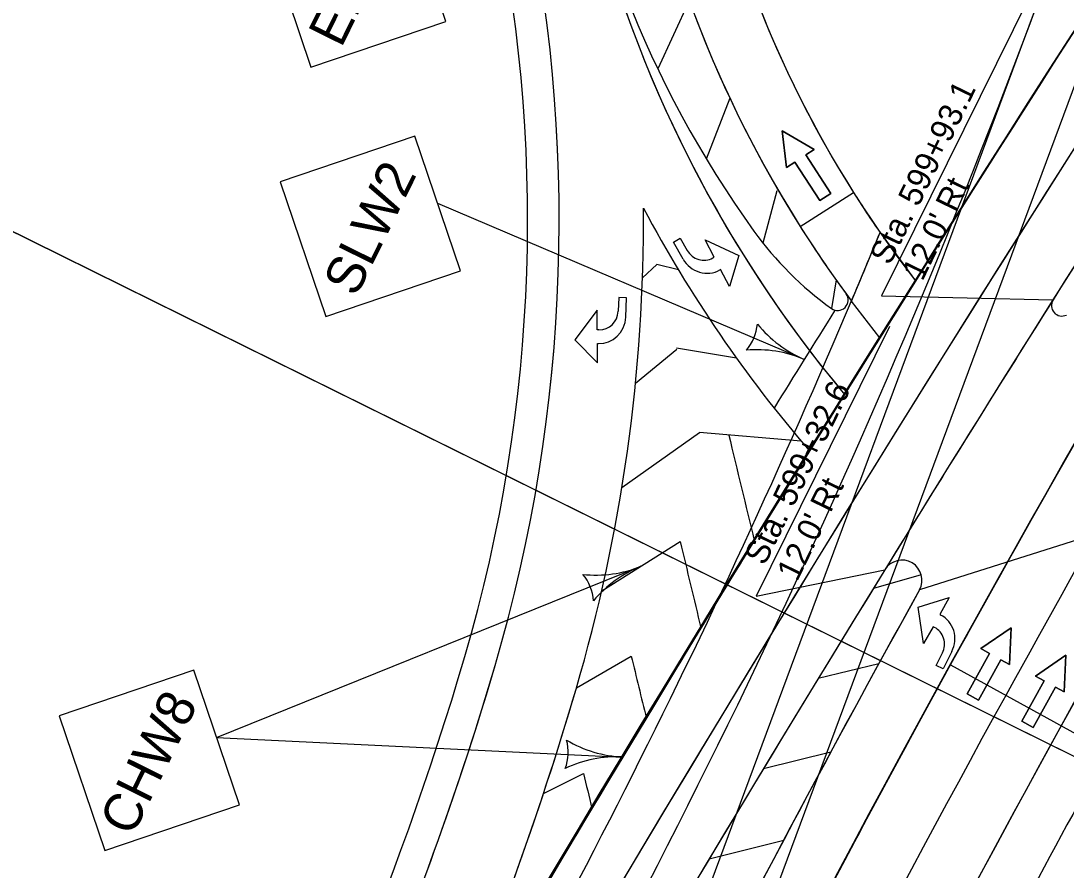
# Model space of a CAD drawing. Extents: x 14097936 to 14128734, y 8632000 to 8683104.
# Drawn here: x 14118895.5 to 14119093.8, y 8668694.3 to 8668855.4 of the extents above; entities that cross this region are included whole.
import ezdxf

# ---------------------------------------------------------------- set-up
doc = ezdxf.new("R2010")
doc.units = 0
for name, color, linetype in [('Cell', 7, 'Continuous'), ('dsn_stg_shd_prev', 7, 'Continuous'), ('dsnNonPlotable', 7, 'Continuous'), ('dsnPaintExistingChannelizingLaneWhite', 7, 'Continuous'), ('dsnPaintExistingChannelizingLaneYellow', 7, 'Continuous'), ('dsnPaintExistingEdgeLineRightWhite', 7, 'Continuous'), ('dsnPaintPlaceBrokenLaneWhite', 7, 'Continuous'), ('dsnPaintPlaceChannelizingLaneWhite', 7, 'Continuous'), ('dsnPaintPlaceChannelizingLaneYellow', 7, 'Continuous'), ('dsnPaintPlaceEdgeLineRightWhite', 7, 'Continuous'), ('dsnPaintPlaceLaneLineWhite', 7, 'Continuous'), ('dsnPaintPlaceStopLineWhite', 7, 'Continuous'), ('dsnShadingPaved', 7, 'Continuous'), ('dsnStdLabel', 7, 'Continuous'), ('dsnStgShadingPrevPav', 7, 'Continuous'), ('dsnStgShadingPropPav', 7, 'Continuous'), ('dsnTapeRemoveChannelizingLaneWhite', 7, 'Continuous'), ('dsnTapeRemoveChannelizingLaneYellow', 7, 'Continuous'), ('Level 2', 7, 'Continuous'), ('Level 5', 7, 'Continuous'), ('Text', 7, 'Continuous')]:
    doc.layers.add(name, color=color, linetype=linetype)

msp = doc.modelspace()

# ---------------------------------------------------------------- linework, layer by layer
at = {"layer": 'Cell'}
for p, q in [((14119026.79, 8668810.43), (14119027.06, 8668810.59)), ((14119028.26, 8668808.25), (14119028.11, 8668808.16)), ((14119005.19, 8668796.79), (14119004.88, 8668796.8)), ((14119004.89, 8668794.17), (14119005.08, 8668794.16)), ((14119069.86, 8668742.74), (14119070.03, 8668742.66)), ((14119068.86, 8668740.3), (14119068.58, 8668740.44))]:
    msp.add_line(p, q, dxfattribs=at)
for points in [[(14119021.16, 8668810.2), (14119019.31, 8668813.39), (14119020.61, 8668814.14), (14119021.92, 8668811.86)], [(14119021.16, 8668810.2), (14119019.31, 8668813.39), (14119020.61, 8668814.14), (14119021.92, 8668811.86)], [(14119027.06, 8668810.59), (14119025.37, 8668813.86), (14119031.72, 8668810.86)], [(14119027.06, 8668810.59), (14119025.37, 8668813.86), (14119031.72, 8668810.86)], [(14119026.79, 8668810.43), (14119027.06, 8668810.59)], [(14119031.72, 8668810.86), (14119029.95, 8668804.97), (14119028.26, 8668808.25)], [(14119031.72, 8668810.86), (14119029.95, 8668804.97), (14119028.26, 8668808.25)], [(14119028.26, 8668808.25), (14119028.11, 8668808.16)], [(14119010.28, 8668799.19), (14119010.45, 8668802.87), (14119008.96, 8668802.93), (14119008.84, 8668800.31)], [(14119010.28, 8668799.19), (14119010.45, 8668802.87), (14119008.96, 8668802.93), (14119008.84, 8668800.31)], [(14119004.88, 8668796.8), (14119004.86, 8668800.48), (14119000.62, 8668794.88)], [(14119004.88, 8668796.8), (14119004.86, 8668800.48), (14119000.62, 8668794.88)], [(14119005.19, 8668796.79), (14119004.88, 8668796.8)], [(14119000.62, 8668794.88), (14119004.91, 8668790.48), (14119004.89, 8668794.17)], [(14119000.62, 8668794.88), (14119004.91, 8668790.48), (14119004.89, 8668794.17)], [(14119004.89, 8668794.17), (14119005.08, 8668794.16)], [(14119065.78, 8668744.17), (14119071.66, 8668745.95), (14119069.86, 8668742.74)], [(14119065.78, 8668744.17), (14119071.66, 8668745.95), (14119069.86, 8668742.74)], [(14119068.58, 8668740.44), (14119066.78, 8668737.22), (14119065.78, 8668744.17)], [(14119068.58, 8668740.44), (14119066.78, 8668737.22), (14119065.78, 8668744.17)], [(14119069.86, 8668742.74), (14119070.03, 8668742.66)], [(14119068.86, 8668740.3), (14119068.58, 8668740.44)], [(14119072.16, 8668735.74), (14119070.53, 8668732.44), (14119069.19, 8668733.1), (14119070.36, 8668735.46)], [(14119072.16, 8668735.74), (14119070.53, 8668732.44), (14119069.19, 8668733.1), (14119070.36, 8668735.46)]]:
    msp.add_lwpolyline(points, dxfattribs=at)
for centre, major_axis, start_param, end_param in [((14119024.94, 8668813.61), (-1.85, 3.18), 1.570796, 3.141593), ((14119024.94, 8668813.61), (-1.85, 3.18), 1.570796, 3.141593), ((14119025.47, 8668812.7), (-2.64, 4.55), 1.570796, 3.141593), ((14119025.47, 8668812.7), (-2.64, 4.55), 1.570796, 3.141593), ((14119005.36, 8668800.46), (0.16, 3.68), 3.141593, 4.712389), ((14119005.36, 8668800.46), (0.16, 3.68), 3.141593, 4.712389), ((14119005.31, 8668799.41), (0.23, 5.25), 3.141593, 4.712389), ((14119005.31, 8668799.41), (0.23, 5.25), 3.141593, 4.712389), ((14119067.7, 8668737.94), (-2.33, -4.71), 1.570796, 3.141593), ((14119067.7, 8668737.94), (-2.33, -4.71), 1.570796, 3.141593), ((14119067.23, 8668737), (-1.63, -3.3), 1.570796, 3.141593), ((14119067.23, 8668737), (-1.63, -3.3), 1.570796, 3.141593)]:
    msp.add_ellipse(centre, major_axis=major_axis, ratio=0.9474, start_param=start_param, end_param=end_param, dxfattribs=at)
at = {"layer": 'dsn_stg_shd_prev'}
msp.add_line((14119071.87, 8668733.2), (14119101.66, 8668716.8), dxfattribs=at)
for centre, radius, start, end in [((14123732.59, 8665873.82), 5512, 146.41866, 157.1633), ((14123732.59, 8665873.82), 5512, 146.50213, 150.36196), ((14121592.11, 8667345.68), 2876.95, 147.23628, 151.16499), ((14121591.75, 8667345.11), 2876.96, 147.23629, 155.33788), ((14118697.65, 8668817.62), 294, 343.6304, 12.5104), ((14118409.81, 8668902.17), 594, 330.3689, 343.63038)]:
    msp.add_arc(centre, radius, start, end, dxfattribs=at)
at = {"layer": 'dsnNonPlotable'}
for points in [[(14118631.64, 8668945.1), (14119326.37, 8670350.23), (14120231.75, 8669902.59), (14119537.02, 8668497.46)], [(14119315.27, 8668607.09), (14120010, 8670012.23), (14119557.31, 8670236.05), (14118862.58, 8668830.91)]]:
    msp.add_lwpolyline(points, close=True, dxfattribs=at)
at = {"layer": 'dsnPaintExistingChannelizingLaneWhite'}
for centre, radius, start, end in [((14118697.65, 8668817.62), 316, 343.6304, 0.4076), ((14118409.81, 8668902.17), 616, 336.56541, 343.63038)]:
    msp.add_arc(centre, radius, start, end, dxfattribs=at)
at = {"layer": 'dsnPaintExistingChannelizingLaneYellow'}
for p, q in [((14119022.33, 8668859.19), (14119016.34, 8668846.32)), ((14119030.03, 8668840.74), (14119025.56, 8668829.19)), ((14119038.93, 8668823.15), (14119036.32, 8668813.23)), ((14119050.18, 8668806.25), (14119049.3, 8668800.81))]:
    msp.add_line(p, q, dxfattribs=at)
for centre, radius, start, end in [((14119196.84, 8668932.46), 200, 186.3366, 215.7802), ((14119233.62, 8668936.54), 225, 186.3042, 216.2139), ((14119087.32, 8668853.53), 65, 215.7802, 234.1997), ((14119050.47, 8668802.43), 2, 234.1997, 36.2139)]:
    msp.add_arc(centre, radius, start, end, dxfattribs=at)
at = {"layer": 'dsnPaintExistingEdgeLineRightWhite'}
for centre, radius, start, end in [((14118697.65, 8668817.62), 300, 343.6304, 12.5104), ((14118409.81, 8668902.17), 600, 334.79009, 343.63038)]:
    msp.add_arc(centre, radius, start, end, dxfattribs=at)
at = {"layer": 'dsnPaintPlaceBrokenLaneWhite'}
for centre, radius, start, end in [((14121592.11, 8667345.68), 2864.95, 147.15737, 151.16499), ((14123732.96, 8665874.38), 5500, 147.11705, 157.1633), ((14121592.11, 8667345.68), 2864.95, 151.16499, 157.1633)]:
    msp.add_arc(centre, radius, start, end, dxfattribs=at)
at = {"layer": 'dsnPaintPlaceChannelizingLaneWhite'}
for p, q in [((14119013.46, 8668806.63), (14119016.17, 8668809.17)), ((14119020.27, 8668808.15), (14119016.17, 8668809.17)), ((14119012.13, 8668786.68), (14119019.96, 8668793.09)), ((14119031.3, 8668791.39), (14119019.92, 8668793.27)), ((14119009.55, 8668766.85), (14119024.28, 8668777.3)), ((14119043.59, 8668775.63), (14119024.28, 8668777.3)), ((14119005.71, 8668747.22), (14119020.62, 8668756.58)), ((14119000.92, 8668728.83), (14119011.33, 8668734.86)), ((14118994.67, 8668708.79), (14119002.26, 8668712.6))]:
    msp.add_line(p, q, dxfattribs=at)
for centre, radius, start, end in [((14119233.62, 8668936.54), 249, 207.9416, 220.8109), ((14124361.64, 8670051.25), 5482, 193.44292, 193.6584), ((14123732.96, 8665874.38), 5512, 148.26304, 149.67774), ((14124353.66, 8670025.82), 5482, 193.38707, 193.56306), ((14124341.15, 8670017.58), 5482, 193.53196, 193.6584), ((14124330.84, 8670000.44), 5482, 193.58699, 193.6584)]:
    msp.add_arc(centre, radius, start, end, dxfattribs=at)
at = {"layer": 'dsnPaintPlaceChannelizingLaneYellow'}
for p, q in [((14119066.36, 8668750.3), (14119057.26, 8668747.71)), ((14119046.82, 8668730.65), (14119058.31, 8668733.44)), ((14119036.44, 8668713.55), (14119049.22, 8668716.7)), ((14119026.13, 8668696.42), (14119040.26, 8668699.96))]:
    msp.add_line(p, q, dxfattribs=at)
for centre, radius, start, end in [((14123732.96, 8665874.38), 5488, 146.41498, 147.75486), ((14119093.05, 8668801.39), 2, 147.7549, 295.2058), ((14119062.69, 8668749.26), 3.81, 330.9739, 148.3847), ((14123748.96, 8665864.73), 5506.68, 148.38653, 150.66501), ((14121592.11, 8667345.68), 2888.95, 150.97391, 155.3184)]:
    msp.add_arc(centre, radius, start, end, dxfattribs=at)
at = {"layer": 'dsnPaintPlaceEdgeLineRightWhite'}
for start, end in [(147.15737, 151.16499), (151.16499, 157.1633)]:
    msp.add_arc((14121592.11, 8667345.68), 2852.95, start, end, dxfattribs=at)
at = {"layer": 'dsnPaintPlaceLaneLineWhite'}
msp.add_arc((14121592.11, 8667345.68), 2876.95, 150.94619, 156.23387, dxfattribs=at)
at = {"layer": 'dsnPaintPlaceStopLineWhite'}
msp.add_arc((14123732.96, 8665874.38), 5522, 148.00263, 148.22799, dxfattribs=at)
at = {"layer": 'dsnShadingPaved'}
for p, q in [((14119043.37, 8668816.41), (14119053.52, 8668822.82)), ((14119043.37, 8668816.41), (14119053.52, 8668822.82)), ((14119058.5, 8668795.27), (14119053.1, 8668802.23)), ((14119051.8, 8668784.52), (14119058.5, 8668795.27)), ((14119045.16, 8668773.8), (14119051.8, 8668784.52))]:
    msp.add_line(p, q, dxfattribs=at)
msp.add_lwpolyline([(14119058.5, 8668795.27), (14119053.1, 8668802.23), (14119058.53, 8668815.24), (14119065.26, 8668806.06)], close=True, dxfattribs=at)
for centre, radius, start, end in [((14123732.96, 8665874.38), 5500, 145.2497, 157.1633), ((14123732.96, 8665874.38), 5488, 145.2497, 157.1633), ((14119233.62, 8668936.54), 237, 167.9329, 219.9002), ((14119233.62, 8668936.54), 225, 167.9329, 212.2703), ((14119233.62, 8668936.54), 225, 167.9329, 212.2703), ((14119233.62, 8668936.54), 213, 167.9329, 212.2703), ((14119233.62, 8668936.54), 213, 167.9329, 217.7768), ((14123732.96, 8665874.38), 5500, 146.42378, 157.1633), ((14121592.11, 8667345.68), 2876.95, 147.15737, 157.1633), ((14121592.11, 8667345.68), 2852.95, 147.15737, 157.1633), ((14123655.03, 8665915.77), 5424.12, 146.80648, 157.24675), ((14119233.62, 8668936.54), 237, 192.5105, 219.9002), ((14123056.19, 8666307.54), 4708.51, 146.80648, 147.95139), ((14118697.65, 8668817.62), 300, 343.6304, 12.5123), ((14119233.62, 8668936.54), 213, 212.2703, 214.7131), ((14121592.11, 8667345.68), 2876.95, 149.16283, 157.1633), ((14118697.65, 8668817.62), 316, 343.6304, 0.4076), ((14119233.62, 8668936.54), 249, 207.9416, 220.8109), ((14119233.62, 8668936.54), 225, 212.2703, 216.6514), ((14119233.62, 8668936.54), 225, 212.2703, 216.6514), ((14117682.33, 8669381.12), 1488, 337.10525, 337.64823), ((14123732.96, 8665874.38), 5488, 147.75486, 148.38471), ((14119093.05, 8668801.39), 2, 147.7549, 295.2058), ((14119062.69, 8668749.26), 3.81, 330.9739, 148.3847), ((14121592.11, 8667345.68), 2888.95, 150.97391, 156.23389), ((14118409.81, 8668902.17), 600, 330.3689, 343.63038), ((14118409.81, 8668902.17), 616, 336.78135, 343.63038)]:
    msp.add_arc(centre, radius, start, end, dxfattribs=at)
at = {"layer": 'dsnStdLabel'}
for p, q in [((14119044.16, 8668791.16), (14118974.6, 8668820.75)), ((14118932.65, 8668719.4), (14119013.16, 8668751.9)), ((14118932.65, 8668719.4), (14119009.72, 8668715.71))]:
    msp.add_line(p, q, dxfattribs=at)
for points in [[(14118950.54, 8668846.65), (14118976.12, 8668855.3), (14118967.47, 8668880.88), (14118941.89, 8668872.22)], [(14118953.35, 8668799.31), (14118978.92, 8668807.96), (14118970.27, 8668833.53), (14118944.7, 8668824.88)], [(14118911.4, 8668697.96), (14118936.97, 8668706.61), (14118928.32, 8668732.19), (14118902.74, 8668723.54)]]:
    msp.add_lwpolyline(points, close=True, dxfattribs=at)
for centre, radius, start, end in [((14119026.45, 8668798.69), 8.86, 319.2251, 354.6935), ((14119053.14, 8668812.28), 22.95, 218.8881, 246.9594), ((14119035.17, 8668770.04), 22.95, 66.9593, 95.0305), ((14119004.57, 8668773.18), 22.95, 263.909, 291.9803), ((14119021.75, 8668730.62), 22.95, 111.9801, 140.0514), ((14118995.32, 8668744.7), 8.86, 4.246, 39.7144), ((14118990.5, 8668716.63), 8.86, 339.5229, 14.9914), ((14119010.82, 8668738.63), 22.95, 239.1859, 267.2572), ((14119008.62, 8668692.79), 22.95, 87.2571, 115.3284)]:
    msp.add_arc(centre, radius, start, end, dxfattribs=at)
at = {"layer": 'dsnStgShadingPrevPav'}
for centre, radius, start, end in [((14123732.96, 8665874.38), 5512, 146.41866, 157.1633), ((14121592.12, 8667345.67), 2876.96, 147.23629, 155.33788)]:
    msp.add_arc(centre, radius, start, end, dxfattribs=at)
at = {"layer": 'dsnStgShadingPropPav'}
msp.add_line((14119071.87, 8668733.2), (14119101.66, 8668716.8), dxfattribs=at)
msp.add_line((14119071.87, 8668733.2), (14119101.66, 8668716.8), dxfattribs=at)
for centre, radius, start, end in [((14123732.59, 8665873.82), 5512, 146.50213, 150.36196), ((14121592.11, 8667345.68), 2876.95, 147.23628, 151.16499), ((14118697.65, 8668817.62), 294, 343.6304, 12.5104), ((14118409.81, 8668902.17), 594, 330.3689, 343.63038), ((14121592.11, 8667345.68), 2876.95, 151.16499, 152.63404), ((14121592.11, 8667345.68), 2842.95, 151.16499, 152.63404)]:
    msp.add_arc(centre, radius, start, end, dxfattribs=at)
at = {"layer": 'dsnTapeRemoveChannelizingLaneWhite'}
msp.add_line((14118983.04, 8668540.5), (14119108.11, 8668877.26), dxfattribs=at)
msp.add_arc((14117682.33, 8669381.12), 1488, 329.20119, 337.13903, dxfattribs=at)
at = {"layer": 'dsnTapeRemoveChannelizingLaneYellow'}
msp.add_line((14118971.78, 8668544.68), (14119088.49, 8668858.92), dxfattribs=at)
msp.add_arc((14117682.32, 8669381.12), 1500, 329.20119, 339.62671, dxfattribs=at)
at = {"layer": 'Level 2'}
for points in [[(14119047.11, 8668821.29), (14119049.21, 8668822.65), (14119044.44, 8668829.99), (14119046.01, 8668831.01), (14119039.98, 8668834.54), (14119040.77, 8668827.6), (14119042.34, 8668828.62)], [(14119075.05, 8668727.73), (14119077.24, 8668726.52), (14119081.48, 8668734.17), (14119083.12, 8668733.26), (14119083.41, 8668740.25), (14119077.65, 8668736.29), (14119079.29, 8668735.38)], [(14119085.42, 8668722.51), (14119087.61, 8668721.3), (14119091.84, 8668728.95), (14119093.48, 8668728.05), (14119093.77, 8668735.03), (14119088.01, 8668731.07), (14119089.65, 8668730.16)]]:
    msp.add_lwpolyline(points, close=True, dxfattribs=at)
at = {"layer": 'Level 5'}
for points in [[(14119042.34, 8668828.62), (14119040.77, 8668827.6), (14119039.98, 8668834.54), (14119046.01, 8668831.01), (14119044.44, 8668829.99), (14119049.21, 8668822.65), (14119047.11, 8668821.29), (14119042.34, 8668828.62)], [(14119079.29, 8668735.38), (14119077.65, 8668736.29), (14119083.41, 8668740.25), (14119083.12, 8668733.26), (14119081.48, 8668734.17), (14119077.24, 8668726.52), (14119075.05, 8668727.73), (14119079.29, 8668735.38)], [(14119089.65, 8668730.16), (14119088.01, 8668731.07), (14119093.77, 8668735.03), (14119093.48, 8668728.05), (14119091.84, 8668728.95), (14119087.61, 8668721.3), (14119085.42, 8668722.51), (14119089.65, 8668730.16)]]:
    msp.add_lwpolyline(points, dxfattribs=at)
at = {"layer": 'Text'}
for points in [[(14119086.91, 8668860.05), (14119058.81, 8668803.21), (14119091.35, 8668802.46)], [(14119060.35, 8668797.43), (14119035.03, 8668746.23), (14119059.45, 8668751.26)], [(14119096.84, 8668709.23), (14119124.94, 8668766.07), (14119066.02, 8668747.42)]]:
    msp.add_lwpolyline(points, dxfattribs=at)

# ---------------------------------------------------------------- texts
at = {"layer": 'dsnStdLabel'}
for s, p in [('ELW4', (14118956.27, 8668850.11)), ('SLW2', (14118959.09, 8668802.79)), ('CHW8', (14118916.62, 8668700.41))]:
    msp.add_text(s, height=7.2, rotation=63.6912, dxfattribs=at).set_placement(p)
at = {"layer": 'Text'}
for s, height, p in [('Sta. 599+93.1', 4.4845, (14119060.4, 8668808.85)), ("12.0' Rt", 4.484, (14119066.56, 8668805.85)), ('Sta. 599+32.6', 4.4845, (14119036.63, 8668751.86)), ("12.0' Rt", 4.484, (14119042.79, 8668748.86))]:
    msp.add_text(s, height=height, rotation=64.04, dxfattribs=at).set_placement(p)

doc.saveas('drawing.dxf')
